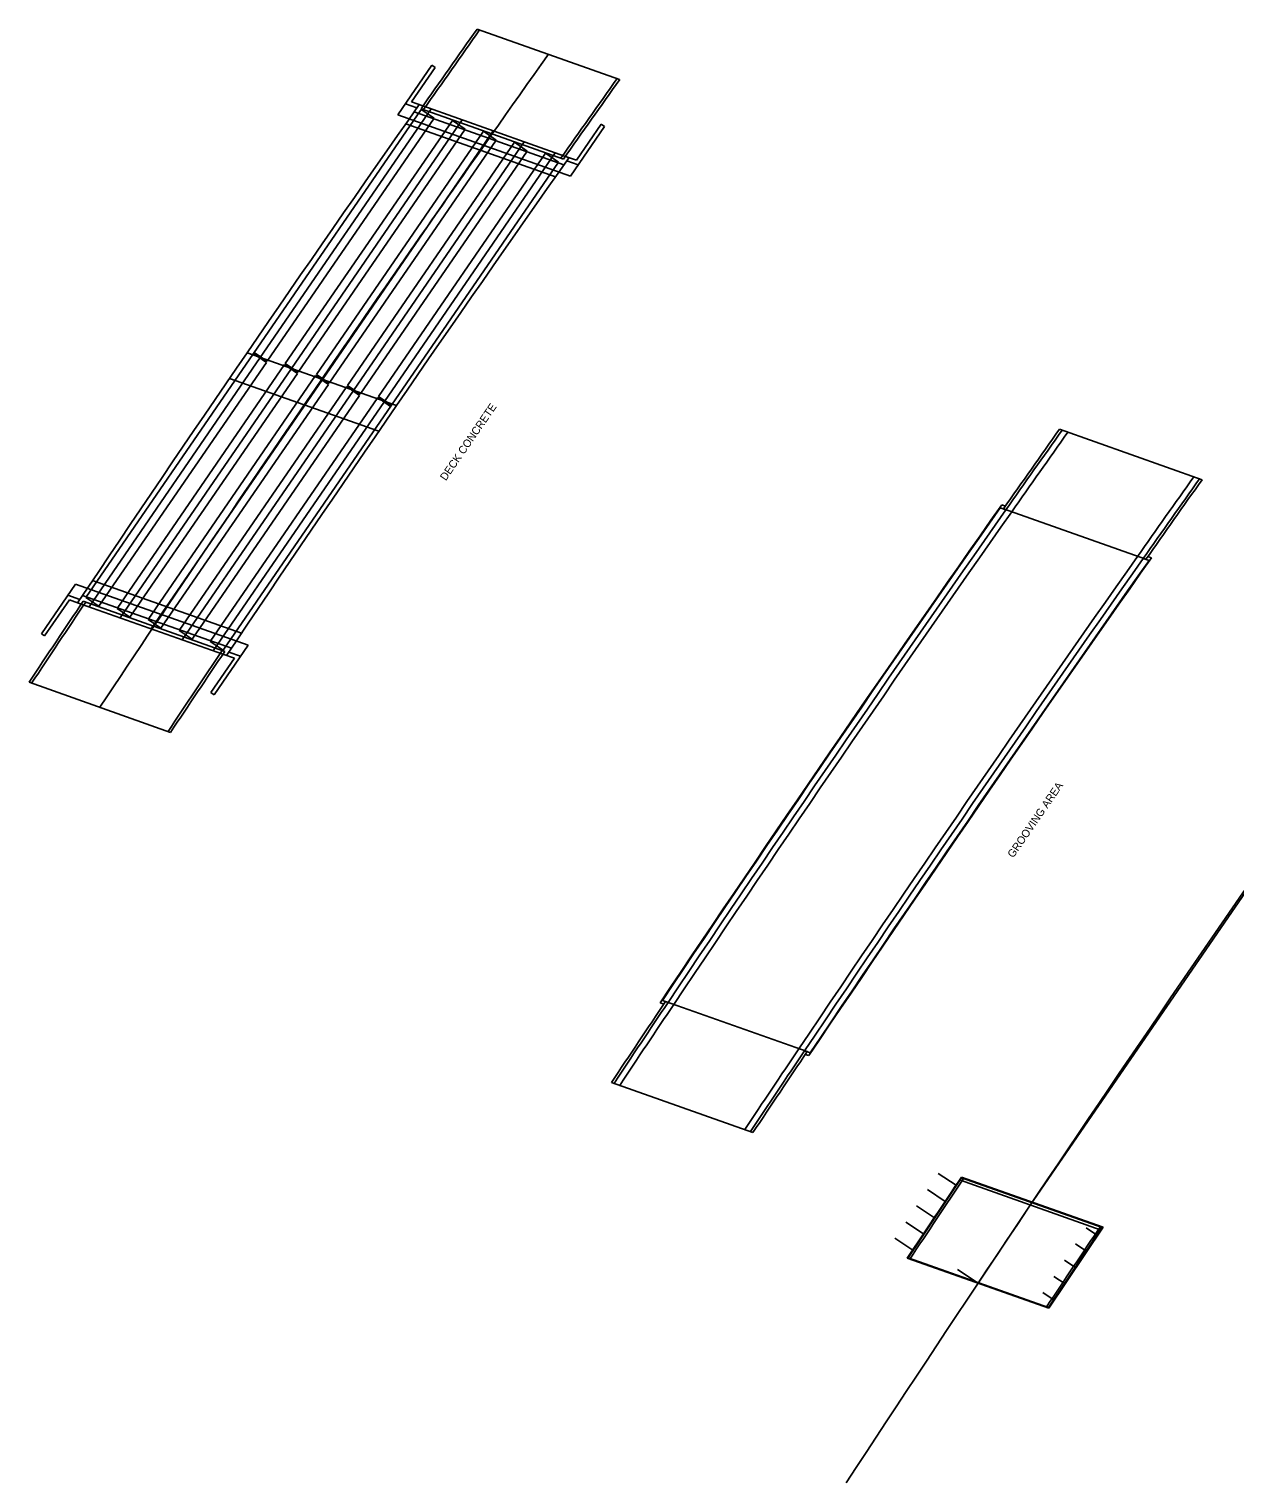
# Model space of a CAD drawing. Extents: x 2378999 to 2381348, y 331302 to 333122.
# Drawn here: x 2379306.1 to 2379615.5, y 332341.7 to 332714.7 of the extents above; entities that cross this region are included whole.
import ezdxf

# ---------------------------------------------------------------- set-up
doc = ezdxf.new("R2010")
doc.units = 0
for name, color, linetype in [('Mis Work Point CELL', 7, 'Continuous'), ('Old_Level_8', 7, 'Continuous'), ('P_NCDOT_Horizontal_Alignment', 7, 'Continuous'), ('P_SMU_Approach_Slab', 7, 'Continuous'), ('P_SMU_Concrete_Barrier_Rail', 7, 'Continuous'), ('P_SMU_Deck', 7, 'Continuous'), ('P_SMU_Mis_Center_Lines', 7, 'Continuous'), ('P_SMU_Mis_L_Lines', 7, 'Continuous'), ('P_SMU_Mis_Long_Chord', 7, 'Continuous'), ('P_SMU_Mis_Short_Chord', 7, 'Continuous'), ('P_SMU_Rebar', 7, 'Continuous'), ('P_SMU_Rebar_B_Bar', 7, 'Continuous'), ('Plan Sheet CELL', 7, 'Continuous'), ('Scratch_Level_0', 7, 'Continuous'), ('Sup Concrete Slab Lines', 7, 'Continuous'), ('Text', 7, 'Continuous')]:
    doc.layers.add(name, color=color, linetype=linetype)

msp = doc.modelspace()

# ---------------------------------------------------------------- linework, layer by layer
at = {"layer": 'Mis Work Point CELL'}
for p, q in [((2379404.97, 332693.49), (2379443.39, 332679.89)), ((2379362.08, 332631.67), (2379400.39, 332618.11)), ((2379319.85, 332569.39), (2379358.05, 332555.87))]:
    msp.add_line(p, q, dxfattribs=at)
at = {"layer": 'Old_Level_8'}
msp.add_line((2379544.39, 332396.46), (2379549.63, 332392.95), dxfattribs=at)
at = {"layer": 'P_NCDOT_Horizontal_Alignment'}
msp.add_arc((2385216.7, 328615.69), 7080, 144.900348, 145.50212, dxfattribs=at)
at = {"layer": 'P_SMU_Approach_Slab'}
for p, q in [((2379421.09, 332714.71), (2379457.67, 332701.77)), ((2379406.7, 332694.29), (2379443.24, 332681.35)), ((2379570.54, 332612.04), (2379607.12, 332599.09)), ((2379556.15, 332591.61), (2379592.69, 332578.68)), ((2379320.01, 332567.92), (2379356.34, 332555.06)), ((2379306.13, 332547.13), (2379342.43, 332534.28)), ((2379469.46, 332465.24), (2379505.79, 332452.39)), ((2379455.58, 332444.46), (2379491.88, 332431.61)), ((2379545.36, 332420.16), (2379581.7, 332407.3)), ((2379531.48, 332399.37), (2379567.78, 332386.53))]:
    msp.add_line(p, q, dxfattribs=at)
for centre, radius, start, end in [((2385216.7, 328615.69), 7098.67, 144.72956, 144.931263), ((2385216.7, 328615.69), 7098, 144.728039, 144.929763), ((2385216.7, 328615.69), 7062, 144.645476, 144.84831), ((2385216.7, 328615.69), 7061.33, 144.643938, 144.846793), ((2385366.14, 328513.01), 7098.67, 144.72956, 144.931263), ((2385366.14, 328513.01), 7098, 144.728039, 144.929763), ((2385366.14, 328513.01), 7062, 144.645476, 144.84831), ((2385366.14, 328513.01), 7061.33, 144.643938, 144.846793), ((2385216.7, 328615.69), 7098.67, 146.168161, 146.369912), ((2385216.7, 328615.69), 7098, 146.166785, 146.368556), ((2385216.7, 328615.69), 7062, 146.092092, 146.294959), ((2385216.7, 328615.69), 7061.33, 146.090701, 146.293589), ((2385366.14, 328513.01), 7098.67, 146.168161, 146.369912), ((2385366.14, 328513.01), 7098, 146.166785, 146.368556), ((2385366.14, 328513.01), 7062, 146.092092, 146.294959), ((2385366.14, 328513.01), 7061.33, 146.090701, 146.293589), ((2385442.05, 328467.93), 7098.67, 146.168161, 146.369912), ((2385442.05, 328467.93), 7098, 146.166785, 146.368556), ((2385442.05, 328467.93), 7062, 146.092092, 146.294959), ((2385442.05, 328467.93), 7061.33, 146.090701, 146.293589)]:
    msp.add_arc(centre, radius, start, end, dxfattribs=at)
at = {"layer": 'P_SMU_Concrete_Barrier_Rail'}
for p, q in [((2379402.81, 332690.42), (2379441.23, 332676.82)), ((2379357.56, 332625.07), (2379395.86, 332611.52)), ((2379555.71, 332592.65), (2379556.64, 332592.32)), ((2379593.19, 332579.38), (2379594.13, 332579.05)), ((2379322.42, 332573.23), (2379360.63, 332559.71)), ((2379468.05, 332464.86), (2379468.98, 332464.53)), ((2379505.31, 332451.67), (2379506.24, 332451.34))]:
    msp.add_line(p, q, dxfattribs=at)
for centre, radius, start, end in [((2385216.7, 328615.69), 7099.63, 144.926438, 146.177079), ((2385216.7, 328615.69), 7060.38, 144.837589, 146.095684), ((2385366.14, 328513.01), 7099.63, 144.926438, 146.177079), ((2385366.14, 328513.01), 7060.38, 144.837589, 146.095684)]:
    msp.add_arc(centre, radius, start, end, dxfattribs=at)
at = {"layer": 'P_SMU_Deck'}
for p, q in [((2379363.72, 332631.47), (2379406.77, 332694.12)), ((2379367.21, 332629.48), (2379410.06, 332691.86)), ((2379410.06, 332691.86), (2379406.77, 332694.12)), ((2379371.88, 332628.92), (2379414.74, 332691.3)), ((2379375.18, 332626.66), (2379418.03, 332689.04)), ((2379379.85, 332626.1), (2379422.71, 332688.48)), ((2379418.03, 332689.04), (2379414.74, 332691.3)), ((2379426, 332686.22), (2379422.71, 332688.48)), ((2379383.15, 332623.84), (2379426, 332686.22)), ((2379387.82, 332623.28), (2379430.68, 332685.66)), ((2379433.97, 332683.4), (2379430.68, 332685.66)), ((2379391.12, 332621.02), (2379433.97, 332683.4)), ((2379395.79, 332620.46), (2379438.65, 332682.84)), ((2379399.09, 332618.2), (2379441.94, 332680.57)), ((2379441.94, 332680.57), (2379438.65, 332682.84)), ((2379367.21, 332629.48), (2379363.91, 332631.74)), ((2379320.73, 332568.9), (2379363.72, 332631.47)), ((2379324.03, 332566.64), (2379367.02, 332629.2)), ((2379328.7, 332566.08), (2379371.69, 332628.65)), ((2379367.02, 332629.2), (2379363.72, 332631.47)), ((2379374.99, 332626.38), (2379371.69, 332628.65)), ((2379375.18, 332626.66), (2379371.88, 332628.92)), ((2379332, 332563.82), (2379374.99, 332626.39)), ((2379336.67, 332563.26), (2379379.66, 332625.83)), ((2379382.96, 332623.56), (2379379.66, 332625.83)), ((2379383.15, 332623.84), (2379379.85, 332626.1)), ((2379339.97, 332561), (2379382.96, 332623.56)), ((2379344.64, 332560.44), (2379387.63, 332623.01)), ((2379347.94, 332558.17), (2379390.93, 332620.74)), ((2379390.93, 332620.74), (2379387.63, 332623.01)), ((2379391.12, 332621.02), (2379387.82, 332623.28)), ((2379399.09, 332618.2), (2379395.79, 332620.46)), ((2379352.61, 332557.62), (2379395.6, 332620.19)), ((2379355.91, 332555.35), (2379399.09, 332618.2)), ((2379398.9, 332617.92), (2379395.6, 332620.19)), ((2379324.03, 332566.64), (2379320.73, 332568.9)), ((2379332, 332563.82), (2379328.7, 332566.08)), ((2379339.97, 332561), (2379336.67, 332563.26)), ((2379347.94, 332558.17), (2379344.64, 332560.44)), ((2379355.91, 332555.35), (2379352.61, 332557.62))]:
    msp.add_line(p, q, dxfattribs=at)
at = {"layer": 'P_SMU_Mis_Center_Lines'}
for p, q in [((2379556.8, 332591.38), (2379555.33, 332591.9)), ((2379592.04, 332578.91), (2379593.51, 332578.39)), ((2379470.11, 332465.01), (2379468.65, 332465.53)), ((2379506.6, 332452.1), (2379505.14, 332452.61))]:
    msp.add_line(p, q, dxfattribs=at)
for radius, start, end in [(7099.5, 144.933138, 146.16988), (7098, 144.929763, 146.166785), (7062, 144.84831, 146.092092), (7060.5, 144.844897, 146.088963)]:
    msp.add_arc((2385366.14, 328513.01), radius, start, end, dxfattribs=at)
at = {"layer": 'P_SMU_Mis_L_Lines'}
for p, q in [((2379365.46, 332630.47), (2379409.28, 332694.26)), ((2379373.43, 332627.65), (2379417.25, 332691.44)), ((2379381.4, 332624.83), (2379425.22, 332688.61)), ((2379389.37, 332622.01), (2379433.19, 332685.79)), ((2379397.34, 332619.19), (2379441.16, 332682.97)), ((2379321.51, 332566.5), (2379365.46, 332630.47)), ((2379329.48, 332563.68), (2379373.43, 332627.65)), ((2379337.45, 332560.86), (2379381.4, 332624.83)), ((2379345.42, 332558.04), (2379389.37, 332622.01)), ((2379353.39, 332555.22), (2379397.34, 332619.19))]:
    msp.add_line(p, q, dxfattribs=at)
at = {"layer": 'P_SMU_Mis_Long_Chord'}
for centre, start, end in [((2385216.7, 328615.69), 144.686866, 146.331854), ((2385442.05, 328467.93), 144.405564, 146.828556)]:
    msp.add_arc(centre, 7080, start, end, dxfattribs=at)
at = {"layer": 'P_SMU_Mis_Short_Chord'}
for p, q in [((2379531.48, 332399.37), (2379545.36, 332420.16)), ((2379539.42, 332421.13), (2379543.98, 332418.08)), ((2379536.64, 332416.97), (2379541.2, 332413.93)), ((2379533.86, 332412.81), (2379538.42, 332409.77)), ((2379549.63, 332392.95), (2379563.53, 332413.73)), ((2379531.09, 332408.65), (2379535.65, 332405.61)), ((2379528.31, 332404.5), (2379532.87, 332401.45)), ((2379567.78, 332386.53), (2379581.7, 332407.3)), ((2379577.39, 332407.17), (2379580.3, 332405.22)), ((2379574.61, 332403.02), (2379577.52, 332401.07)), ((2379571.83, 332398.86), (2379574.74, 332396.91)), ((2379569.05, 332394.71), (2379571.96, 332392.76)), ((2379566.27, 332390.55), (2379569.17, 332388.6))]:
    msp.add_line(p, q, dxfattribs=at)
at = {"layer": 'P_SMU_Rebar'}
for radius, start, end in [(7096.5, 144.724616, 144.926386), (7063.5, 144.648933, 144.851721), (7096.5, 144.926386, 146.163688), (7063.5, 144.851721, 146.09522), (7096.5, 146.163688, 146.365505), (7063.5, 146.09522, 146.298041)]:
    msp.add_arc((2385366.14, 328513.01), radius, start, end, dxfattribs=at)
at = {"layer": 'P_SMU_Rebar_B_Bar'}
for p, q in [((2379400.73, 332692.69), (2379409.48, 332705.42)), ((2379404.25, 332696.04), (2379410.31, 332704.85)), ((2379410.31, 332704.85), (2379409.48, 332705.42)), ((2379402.69, 332695.53), (2379405.66, 332694.48)), ((2379404.25, 332696.04), (2379407.2, 332694.99)), ((2379445.04, 332677), (2379400.73, 332692.69)), ((2379407.2, 332694.99), (2379443.74, 332682.06)), ((2379445.04, 332677), (2379453.79, 332689.74)), ((2379446.61, 332681.05), (2379452.97, 332690.3)), ((2379452.97, 332690.3), (2379453.79, 332689.74)), ((2379446.61, 332681.05), (2379443.74, 332682.06)), ((2379446.99, 332679.85), (2379444.08, 332680.88)), ((2379318.04, 332572.33), (2379309.29, 332559.59)), ((2379318.04, 332572.33), (2379362.35, 332556.65)), ((2379316.48, 332568.29), (2379310.12, 332559.03)), ((2379316.09, 332569.48), (2379319.18, 332568.39)), ((2379316.48, 332568.29), (2379319.53, 332567.21)), ((2379319.53, 332567.21), (2379355.86, 332554.35)), ((2379310.12, 332559.03), (2379309.29, 332559.59)), ((2379362.35, 332556.65), (2379353.6, 332543.91)), ((2379358.83, 332553.3), (2379355.86, 332554.35)), ((2379360.4, 332553.8), (2379357.37, 332554.87)), ((2379358.83, 332553.3), (2379352.78, 332544.48)), ((2379352.78, 332544.48), (2379353.6, 332543.91)), ((2379544.88, 332419.45), (2379581.22, 332406.59))]:
    msp.add_line(p, q, dxfattribs=at)
at = {"layer": 'Plan Sheet CELL'}
msp.add_line((2379563.05, 332413.02), (2379650.82, 332540.77), dxfattribs=at)
at = {"layer": 'Scratch_Level_0'}
for p, q in [((2379545.43, 332419.96), (2379581.44, 332407.22)), ((2379531.74, 332399.46), (2379567.72, 332386.73))]:
    msp.add_line(p, q, dxfattribs=at)
for radius, start, end in [(7098.5, 146.169205, 146.368186), (7061.5, 146.092445, 146.292536)]:
    msp.add_arc((2385442.05, 328467.93), radius, start, end, dxfattribs=at)
at = {"layer": 'Text'}
msp.add_line((2379338.94, 332562.63), (2379338.94, 332562.63), dxfattribs=at)

# ---------------------------------------------------------------- texts
at = {"layer": 'Sup Concrete Slab Lines'}
for s, p in [('DECK CONCRETE', (2379413.07, 332598.69)), ('GROOVING AREA', (2379558.67, 332501.92))]:
    msp.add_text(s, height=2, rotation=55.5093, dxfattribs=at).set_placement(p)

doc.saveas('drawing.dxf')
